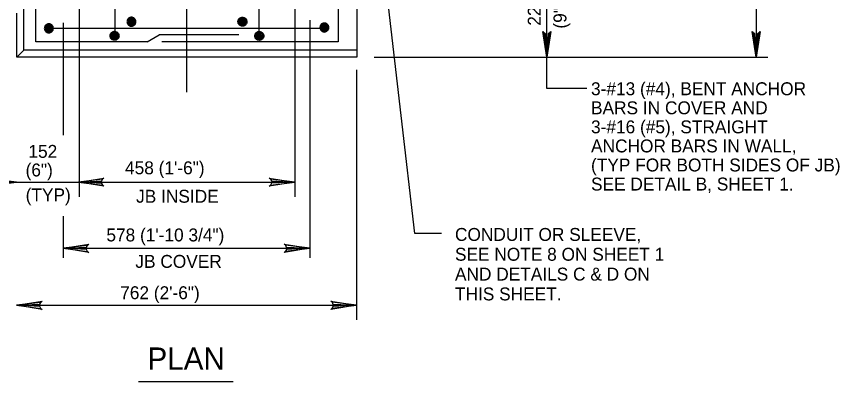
# Model space of a CAD drawing. Extents: x 638455 to 640199, y 298558 to 299152.
# Drawn here: x 639455 to 639669, y 298861 to 298956 of the extents above; entities that cross this region are included whole.
import ezdxf

# ---------------------------------------------------------------- set-up
doc = ezdxf.new("R2010")
doc.units = 0
for name, color, linetype in [('1', 7, 'Continuous'), ('2', 7, 'Continuous'), ('3', 7, 'Continuous')]:
    doc.layers.add(name, color=color, linetype=linetype)

msp = doc.modelspace()

# ---------------------------------------------------------------- linework, layer by layer
at = {"layer": '1'}
msp.add_line((639488.97, 298949.41), (639492.13, 298951.22), dxfattribs=at)
at = {"layer": '2'}
for p, q in [((639543.52, 299065.79), (639543.52, 298945.42)), ((639647.33, 299065.79), (639647.33, 298945.42)), ((639459.98, 298949.41), (639459.98, 299061.88)), ((639538.66, 299061.88), (639538.66, 298949.41)), ((639558.58, 298899.51), (639546.71, 299001.76)), ((639480.58, 298993.32), (639480.58, 298951.85)), ((639518.05, 298989.74), (639518.05, 298951.85)), ((639592.9, 298937.26), (639592.9, 298971.53)), ((639456.92, 298947.23), (639456.92, 298958.24)), ((639471.27, 298959.27), (639471.27, 298909.03)), ((639499.18, 298958.91), (639499.18, 298936.34)), ((639527.36, 298959.27), (639527.36, 298909.03)), ((639455.11, 298945.42), (639455.11, 298956.88)), ((639467.11, 298954.32), (639467.11, 298925.1)), ((639531.26, 298955.03), (639531.26, 298893.2)), ((639463.26, 298952.92), (639535.12, 298952.92)), ((639488.97, 298949.41), (639459.98, 298949.41)), ((639512.82, 298951.22), (639492.13, 298951.22)), ((639538.66, 298949.41), (639492.82, 298949.41)), ((639456.92, 298947.23), (639455.11, 298945.42)), ((639543.52, 298945.42), (639455.11, 298945.42)), ((639548.01, 298945.42), (639650.39, 298945.42)), ((639543.38, 298942.13), (639543.38, 298877.08)), ((639603.29, 298937.26), (639592.9, 298937.26)), ((639444.36, 298912.89), (639454.98, 298912.89)), ((639454.98, 298912.89), (639471.09, 298912.89)), ((639471.09, 298912.89), (639527.36, 298912.89)), ((639467.11, 298904.08), (639467.11, 298893.2)), ((639565.55, 298899.51), (639558.58, 298899.51)), ((639467.11, 298895.67), (639531.26, 298895.67)), ((639454.98, 298880.84), (639543.38, 298880.84))]:
    msp.add_line(p, q, dxfattribs=at)
for points in [[(639593.69, 298951.75), (639593.24, 298951.52), (639592.9, 298945.42), (639593.69, 298951.75), (639593.97, 298952.08), (639592.9, 298945.42), (639592.6, 298951.51), (639592.14, 298951.73), (639592.9, 298945.42), (639591.84, 298952.08), (639592.14, 298951.73)], [(639648.12, 298951.75), (639647.66, 298951.52), (639647.33, 298945.42), (639648.12, 298951.75), (639648.4, 298952.08), (639647.33, 298945.42), (639647.03, 298951.51), (639646.57, 298951.73), (639647.33, 298945.42), (639646.27, 298952.08), (639646.57, 298951.73)], [(639543.52, 298947.23), (639456.92, 298947.23)], [(639448.65, 298913.68), (639448.89, 298913.22), (639454.98, 298912.89), (639448.65, 298913.68), (639448.33, 298913.96), (639454.98, 298912.89), (639448.89, 298912.59), (639448.67, 298912.13), (639454.98, 298912.89), (639448.33, 298911.83), (639448.67, 298912.13)], [(639477.42, 298912.09), (639477.18, 298912.55), (639471.09, 298912.89), (639477.42, 298912.09), (639477.74, 298911.81), (639471.09, 298912.89), (639477.18, 298913.19), (639477.4, 298913.64), (639471.09, 298912.89), (639477.74, 298913.94), (639477.4, 298913.64)], [(639521.03, 298913.68), (639521.27, 298913.22), (639527.36, 298912.89), (639521.03, 298913.68), (639520.71, 298913.96), (639527.36, 298912.89), (639521.27, 298912.59), (639521.05, 298912.13), (639527.36, 298912.89), (639520.71, 298911.83), (639521.05, 298912.13)], [(639473.44, 298894.88), (639473.2, 298895.34), (639467.11, 298895.67), (639473.44, 298894.88), (639473.76, 298894.6), (639467.11, 298895.67), (639473.2, 298895.97), (639473.42, 298896.42), (639467.11, 298895.67), (639473.76, 298896.73), (639473.42, 298896.42)], [(639524.93, 298896.46), (639525.16, 298896.01), (639531.26, 298895.67), (639524.93, 298896.46), (639524.6, 298896.74), (639531.26, 298895.67), (639525.17, 298895.37), (639524.95, 298894.92), (639531.26, 298895.67), (639524.6, 298894.61), (639524.95, 298894.92)], [(639461.31, 298880.05), (639461.07, 298880.5), (639454.98, 298880.84), (639461.31, 298880.05), (639461.64, 298879.77), (639454.98, 298880.84), (639461.07, 298881.14), (639461.29, 298881.59), (639454.98, 298880.84), (639461.64, 298881.9), (639461.29, 298881.59)], [(639537.05, 298881.63), (639537.29, 298881.18), (639543.38, 298880.84), (639537.05, 298881.63), (639536.73, 298881.91), (639543.38, 298880.84), (639537.29, 298880.54), (639537.07, 298880.09), (639543.38, 298880.84), (639536.73, 298879.78), (639537.07, 298880.09)]]:
    msp.add_lwpolyline(points, dxfattribs=at)
for points in [[(639484.89, 298954.62), (639484.95, 298954.51), (639485.03, 298954.52), (639485.05, 298954.7), (639484.89, 298954.8), (639484.7, 298954.7), (639484.71, 298954.52), (639484.81, 298954.41), (639485.03, 298954.39), (639485.19, 298954.51), (639485.26, 298954.69), (639485.15, 298954.94), (639484.91, 298955), (639484.64, 298954.92), (639484.5, 298954.75), (639484.52, 298954.46), (639484.65, 298954.28), (639484.89, 298954.21), (639485.11, 298954.26), (639485.28, 298954.37), (639485.36, 298954.55), (639485.41, 298954.79), (639485.35, 298955.02), (639485.14, 298955.16), (639484.82, 298955.22), (639484.47, 298955.08), (639484.3, 298954.84), (639484.3, 298954.51), (639484.41, 298954.23), (639484.65, 298954.04), (639485.03, 298954.02), (639485.31, 298954.17), (639485.47, 298954.43), (639485.57, 298954.7), (639485.52, 298955.03), (639485.31, 298955.27), (639484.99, 298955.4), (639484.48, 298955.32), (639484.17, 298955.04), (639484.1, 298954.66), (639484.17, 298954.28), (639484.39, 298953.99), (639484.68, 298953.87), (639485.14, 298953.87), (639485.5, 298954.08), (639485.68, 298954.39), (639485.72, 298954.72), (639485.69, 298955), (639485.58, 298955.3), (639485.28, 298955.52), (639484.8, 298955.58), (639484.37, 298955.46), (639484.06, 298955.17), (639483.93, 298954.82), (639483.96, 298954.38), (639484.1, 298953.96), (639484.34, 298953.79), (639484.77, 298953.64), (639485.21, 298953.7), (639485.52, 298953.84), (639485.75, 298954.12), (639485.88, 298954.4), (639485.88, 298954.7), (639485.86, 298955.03), (639485.79, 298955.34), (639485.63, 298955.52), (639485.39, 298955.67), (639485.15, 298955.76), (639484.91, 298955.79), (639484.61, 298955.75), (639484.3, 298955.65), (639484.03, 298955.45), (639483.85, 298955.2), (639483.76, 298954.89), (639483.72, 298954.6), (639483.78, 298954.26), (639483.91, 298953.99), (639484.12, 298953.74), (639484.39, 298953.57), (639484.65, 298953.47), (639484.96, 298953.46), (639485.33, 298953.55), (639485.63, 298953.74), (639485.82, 298953.93), (639485.97, 298954.18), (639486.03, 298954.44), (639486.04, 298954.75), (639485.97, 298955.08), (639485.88, 298955.23), (639485.68, 298955.45)], [(639513.74, 298954.62), (639513.68, 298954.51), (639513.6, 298954.52), (639513.58, 298954.7), (639513.74, 298954.8), (639513.93, 298954.7), (639513.93, 298954.52), (639513.82, 298954.41), (639513.6, 298954.39), (639513.44, 298954.51), (639513.37, 298954.69), (639513.48, 298954.94), (639513.72, 298955), (639513.99, 298954.92), (639514.13, 298954.75), (639514.11, 298954.46), (639513.98, 298954.28), (639513.74, 298954.21), (639513.52, 298954.26), (639513.35, 298954.37), (639513.27, 298954.55), (639513.23, 298954.79), (639513.28, 298955.02), (639513.49, 298955.16), (639513.81, 298955.22), (639514.16, 298955.08), (639514.33, 298954.84), (639514.33, 298954.51), (639514.22, 298954.23), (639513.98, 298954.04), (639513.6, 298954.02), (639513.32, 298954.17), (639513.16, 298954.43), (639513.06, 298954.7), (639513.11, 298955.03), (639513.32, 298955.27), (639513.64, 298955.4), (639514.15, 298955.32), (639514.46, 298955.04), (639514.53, 298954.66), (639514.46, 298954.28), (639514.24, 298953.99), (639513.95, 298953.87), (639513.49, 298953.87), (639513.13, 298954.08), (639512.96, 298954.39), (639512.91, 298954.72), (639512.94, 298955), (639513.05, 298955.3), (639513.35, 298955.52), (639513.83, 298955.58), (639514.26, 298955.46), (639514.57, 298955.17), (639514.7, 298954.82), (639514.67, 298954.38), (639514.53, 298953.96), (639514.29, 298953.79), (639513.86, 298953.64), (639513.42, 298953.7), (639513.12, 298953.84), (639512.88, 298954.12), (639512.75, 298954.4), (639512.75, 298954.7), (639512.77, 298955.03), (639512.84, 298955.34), (639513, 298955.52), (639513.24, 298955.67), (639513.48, 298955.76), (639513.72, 298955.79), (639514.02, 298955.75), (639514.33, 298955.65), (639514.6, 298955.45), (639514.78, 298955.2), (639514.87, 298954.89), (639514.91, 298954.6), (639514.85, 298954.26), (639514.72, 298953.99), (639514.51, 298953.74), (639514.24, 298953.57), (639513.98, 298953.47), (639513.67, 298953.46), (639513.3, 298953.55), (639513, 298953.74), (639512.81, 298953.93), (639512.66, 298954.18), (639512.6, 298954.44), (639512.59, 298954.75), (639512.66, 298955.08), (639512.75, 298955.23), (639512.96, 298955.45)], [(639463.4, 298952.92), (639463.46, 298952.8), (639463.55, 298952.81), (639463.57, 298953), (639463.4, 298953.1), (639463.21, 298953), (639463.22, 298952.81), (639463.33, 298952.7), (639463.55, 298952.68), (639463.7, 298952.8), (639463.78, 298952.99), (639463.67, 298953.24), (639463.42, 298953.29), (639463.15, 298953.21), (639463.01, 298953.04), (639463.03, 298952.76), (639463.17, 298952.57), (639463.4, 298952.51), (639463.62, 298952.55), (639463.8, 298952.66), (639463.87, 298952.85), (639463.92, 298953.09), (639463.87, 298953.31), (639463.66, 298953.45), (639463.33, 298953.51), (639462.99, 298953.37), (639462.81, 298953.13), (639462.81, 298952.8), (639462.92, 298952.52), (639463.17, 298952.33), (639463.55, 298952.31), (639463.82, 298952.46), (639463.98, 298952.72), (639464.08, 298953), (639464.04, 298953.33), (639463.82, 298953.56), (639463.5, 298953.69), (639463, 298953.61), (639462.68, 298953.34), (639462.62, 298952.95), (639462.68, 298952.57), (639462.9, 298952.28), (639463.19, 298952.16), (639463.66, 298952.17), (639464.02, 298952.38), (639464.19, 298952.68), (639464.23, 298953.01), (639464.2, 298953.29), (639464.09, 298953.6), (639463.8, 298953.81), (639463.32, 298953.88), (639462.89, 298953.75), (639462.57, 298953.46), (639462.44, 298953.11), (639462.47, 298952.67), (639462.62, 298952.26), (639462.86, 298952.08), (639463.28, 298951.93), (639463.72, 298951.99), (639464.03, 298952.14), (639464.27, 298952.41), (639464.39, 298952.69), (639464.39, 298953), (639464.38, 298953.33), (639464.3, 298953.64), (639464.14, 298953.81), (639463.91, 298953.96), (639463.67, 298954.05), (639463.42, 298954.09), (639463.12, 298954.04), (639462.81, 298953.94), (639462.55, 298953.75), (639462.37, 298953.5), (639462.28, 298953.19), (639462.23, 298952.89), (639462.3, 298952.55), (639462.42, 298952.28), (639462.64, 298952.03), (639462.9, 298951.86), (639463.17, 298951.76), (639463.48, 298951.75), (639463.84, 298951.84), (639464.14, 298952.03), (639464.33, 298952.22), (639464.49, 298952.47), (639464.54, 298952.74), (639464.55, 298953.04), (639464.49, 298953.37), (639464.39, 298953.52), (639464.19, 298953.75)], [(639535.06, 298953.12), (639535.12, 298953.01), (639535.21, 298953.02), (639535.23, 298953.2), (639535.07, 298953.3), (639534.87, 298953.2), (639534.88, 298953.02), (639534.99, 298952.91), (639535.21, 298952.89), (639535.36, 298953.01), (639535.44, 298953.19), (639535.33, 298953.44), (639535.08, 298953.5), (639534.82, 298953.42), (639534.68, 298953.25), (639534.69, 298952.96), (639534.83, 298952.78), (639535.07, 298952.71), (639535.28, 298952.76), (639535.46, 298952.87), (639535.54, 298953.05), (639535.58, 298953.29), (639535.53, 298953.52), (639535.32, 298953.66), (639535, 298953.72), (639534.65, 298953.58), (639534.48, 298953.34), (639534.48, 298953.01), (639534.59, 298952.73), (639534.83, 298952.54), (639535.21, 298952.52), (639535.48, 298952.67), (639535.65, 298952.93), (639535.75, 298953.2), (639535.7, 298953.53), (639535.48, 298953.77), (639535.17, 298953.9), (639534.66, 298953.82), (639534.34, 298953.54), (639534.28, 298953.16), (639534.34, 298952.78), (639534.57, 298952.49), (639534.86, 298952.37), (639535.32, 298952.37), (639535.68, 298952.58), (639535.85, 298952.89), (639535.9, 298953.22), (639535.87, 298953.5), (639535.76, 298953.8), (639535.46, 298954.02), (639534.98, 298954.08), (639534.55, 298953.96), (639534.23, 298953.67), (639534.1, 298953.32), (639534.14, 298952.88), (639534.28, 298952.46), (639534.52, 298952.29), (639534.94, 298952.14), (639535.38, 298952.2), (639535.69, 298952.34), (639535.93, 298952.62), (639536.06, 298952.9), (639536.06, 298953.2), (639536.04, 298953.53), (639535.96, 298953.84), (639535.81, 298954.02), (639535.57, 298954.17), (639535.33, 298954.26), (639535.08, 298954.29), (639534.78, 298954.25), (639534.48, 298954.15), (639534.21, 298953.96), (639534.03, 298953.71), (639533.94, 298953.39), (639533.89, 298953.1), (639533.96, 298952.76), (639534.08, 298952.49), (639534.3, 298952.24), (639534.57, 298952.07), (639534.83, 298951.97), (639535.14, 298951.96), (639535.51, 298952.05), (639535.81, 298952.24), (639536, 298952.43), (639536.15, 298952.68), (639536.21, 298952.94), (639536.21, 298953.25), (639536.15, 298953.58), (639536.06, 298953.73), (639535.85, 298953.96)], [(639480.49, 298950.97), (639480.55, 298951.09), (639480.64, 298951.07), (639480.66, 298950.89), (639480.5, 298950.79), (639480.3, 298950.89), (639480.31, 298951.07), (639480.42, 298951.18), (639480.64, 298951.2), (639480.79, 298951.09), (639480.87, 298950.9), (639480.76, 298950.65), (639480.52, 298950.6), (639480.25, 298950.67), (639480.11, 298950.85), (639480.12, 298951.13), (639480.26, 298951.31), (639480.5, 298951.38), (639480.71, 298951.34), (639480.89, 298951.23), (639480.97, 298951.04), (639481.01, 298950.8), (639480.96, 298950.58), (639480.75, 298950.43), (639480.43, 298950.37), (639480.08, 298950.51), (639479.91, 298950.76), (639479.91, 298951.09), (639480.02, 298951.37), (639480.26, 298951.55), (639480.64, 298951.58), (639480.91, 298951.42), (639481.08, 298951.16), (639481.17, 298950.89), (639481.13, 298950.56), (639480.91, 298950.33), (639480.6, 298950.19), (639480.09, 298950.27), (639479.78, 298950.55), (639479.71, 298950.93), (639479.78, 298951.31), (639479.99, 298951.61), (639480.29, 298951.73), (639480.75, 298951.72), (639481.11, 298951.51), (639481.28, 298951.2), (639481.33, 298950.87), (639481.3, 298950.6), (639481.18, 298950.29), (639480.89, 298950.08), (639480.41, 298950.01), (639479.98, 298950.13), (639479.66, 298950.42), (639479.53, 298950.77), (639479.57, 298951.21), (639479.71, 298951.63), (639479.95, 298951.8), (639480.37, 298951.95), (639480.81, 298951.89), (639481.12, 298951.75), (639481.36, 298951.48), (639481.48, 298951.19), (639481.48, 298950.89), (639481.47, 298950.56), (639481.4, 298950.25), (639481.24, 298950.08), (639481, 298949.92), (639480.76, 298949.83), (639480.52, 298949.8), (639480.21, 298949.85), (639479.91, 298949.94), (639479.64, 298950.14), (639479.46, 298950.39), (639479.37, 298950.7), (639479.33, 298951), (639479.39, 298951.34), (639479.51, 298951.61), (639479.73, 298951.86), (639479.99, 298952.03), (639480.26, 298952.12), (639480.57, 298952.13), (639480.93, 298952.04), (639481.24, 298951.86), (639481.42, 298951.66), (639481.58, 298951.41), (639481.63, 298951.15), (639481.65, 298950.85), (639481.58, 298950.51), (639481.48, 298950.36), (639481.28, 298950.14)], [(639518.14, 298950.95), (639518.2, 298951.07), (639518.29, 298951.06), (639518.3, 298950.87), (639518.14, 298950.77), (639517.95, 298950.87), (639517.96, 298951.06), (639518.06, 298951.17), (639518.29, 298951.19), (639518.44, 298951.07), (639518.51, 298950.88), (639518.4, 298950.63), (639518.16, 298950.58), (639517.89, 298950.66), (639517.75, 298950.83), (639517.77, 298951.11), (639517.9, 298951.3), (639518.14, 298951.36), (639518.36, 298951.32), (639518.54, 298951.21), (639518.61, 298951.02), (639518.66, 298950.79), (639518.6, 298950.56), (639518.39, 298950.42), (639518.07, 298950.36), (639517.72, 298950.5), (639517.55, 298950.74), (639517.55, 298951.07), (639517.66, 298951.35), (639517.9, 298951.54), (639518.29, 298951.56), (639518.56, 298951.41), (639518.72, 298951.15), (639518.82, 298950.87), (639518.78, 298950.55), (639518.56, 298950.31), (639518.24, 298950.18), (639517.74, 298950.26), (639517.42, 298950.53), (639517.35, 298950.92), (639517.42, 298951.3), (639517.64, 298951.59), (639517.93, 298951.71), (639518.39, 298951.7), (639518.75, 298951.49), (639518.93, 298951.19), (639518.97, 298950.86), (639518.94, 298950.58), (639518.83, 298950.27), (639518.54, 298950.06), (639518.05, 298950), (639517.62, 298950.12), (639517.31, 298950.41), (639517.18, 298950.76), (639517.21, 298951.2), (639517.35, 298951.61), (639517.6, 298951.79), (639518.02, 298951.94), (639518.46, 298951.88), (639518.77, 298951.74), (639519, 298951.46), (639519.13, 298951.18), (639519.13, 298950.87), (639519.11, 298950.55), (639519.04, 298950.24), (639518.89, 298950.06), (639518.64, 298949.91), (639518.4, 298949.82), (639518.16, 298949.78), (639517.86, 298949.83), (639517.55, 298949.93), (639517.29, 298950.12), (639517.1, 298950.37), (639517.01, 298950.69), (639516.97, 298950.98), (639517.04, 298951.32), (639517.16, 298951.59), (639517.38, 298951.84), (639517.64, 298952.01), (639517.9, 298952.11), (639518.21, 298952.12), (639518.58, 298952.03), (639518.89, 298951.84), (639519.07, 298951.65), (639519.23, 298951.4), (639519.28, 298951.13), (639519.29, 298950.83), (639519.23, 298950.5), (639519.13, 298950.35), (639518.93, 298950.12)]]:
    msp.add_spline(points, degree=3, dxfattribs=at)
at = {"layer": '3'}
msp.add_line((639486.72, 298861.01), (639511.34, 298861.01), dxfattribs=at)

# ---------------------------------------------------------------- texts
for s, p in [('225', (639591.32, 298953.59)), ('(9")', (639598.01, 298952.84))]:
    msp.add_text(s, height=3.36, rotation=90, dxfattribs=at).set_placement(p)
for s, height, p in [('3-#13 (#4), BENT ANCHOR', 3.36, (639604.4, 298935.51)), ('BARS IN COVER AND', 3.36, (639604.4, 298930.55)), ('3-#16 (#5), STRAIGHT', 3.36, (639604.4, 298925.59)), ('ANCHOR BARS IN WALL,', 3.36, (639604.4, 298920.63)), ('152', 3.36, (639458.09, 298919.22)), ('(TYP FOR BOTH SIDES OF JB)', 3.36, (639604.4, 298915.67)), ('(6")', 3.36, (639457.35, 298914.38)), ('458 (1\'-6")', 3.36, (639483.22, 298914.94)), ('SEE DETAIL B, SHEET 1.', 3.36, (639604.4, 298910.71)), ('(TYP)', 3.36, (639457.37, 298907.89)), ('JB INSIDE', 3.36, (639486.1, 298907.53)), ('578 (1\'-10 3/4")', 3.36, (639478.37, 298897.47)), ('CONDUIT OR SLEEVE,', 3.36, (639569.02, 298897.6)), ('SEE NOTE 8 ON SHEET 1', 3.36, (639569.02, 298892.44)), ('JB COVER', 3.36, (639485.91, 298890.59)), ('AND DETAILS C & D ON', 3.36, (639569.02, 298887.28)), ('762 (2\'-6")', 3.36, (639481.96, 298882.44)), ('THIS SHEET.', 3.36, (639569.02, 298882.12)), ('PLAN', 5.76, (639489.05, 298864.11))]:
    msp.add_text(s, height=height, dxfattribs=at).set_placement(p)

doc.saveas('drawing.dxf')
